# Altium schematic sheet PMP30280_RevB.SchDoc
size 431 x 279 mm; Date: Not shown in title block; ApprovedBy: Not shown in title block; CheckedBy: Not shown in title block; Author: Not shown in title block; CompanyName: Not shown in title block; Engineer: Not shown in title block; Organization: Not shown in title block; Address1: Not shown in title block; Address2: Not shown in title block; Address3: Not shown in title block; Address4: Not shown in title block; DocumentNumber: 1; Revision: Use project parameter SCH_Rev; SheetNumber: 2; SheetTotal: 3; PageSetup: Record=PageOptions¦CenterHorizontal=True¦CenterVertical=True¦PrintScale=1.00¦XCorrection=1.00¦YCorrection=1.00¦PrintKind=0¦BorderSize=5000000¦LeftOffset=0¦BottomOffset=0¦Orientation=2¦PaperLength=1000¦PaperWidth=1000¦Scale=100¦PaperSource=15¦PrintQuality=600¦MediaType=1¦DitherType=10¦PaperKind=Letter¦PrintScaleMode=1
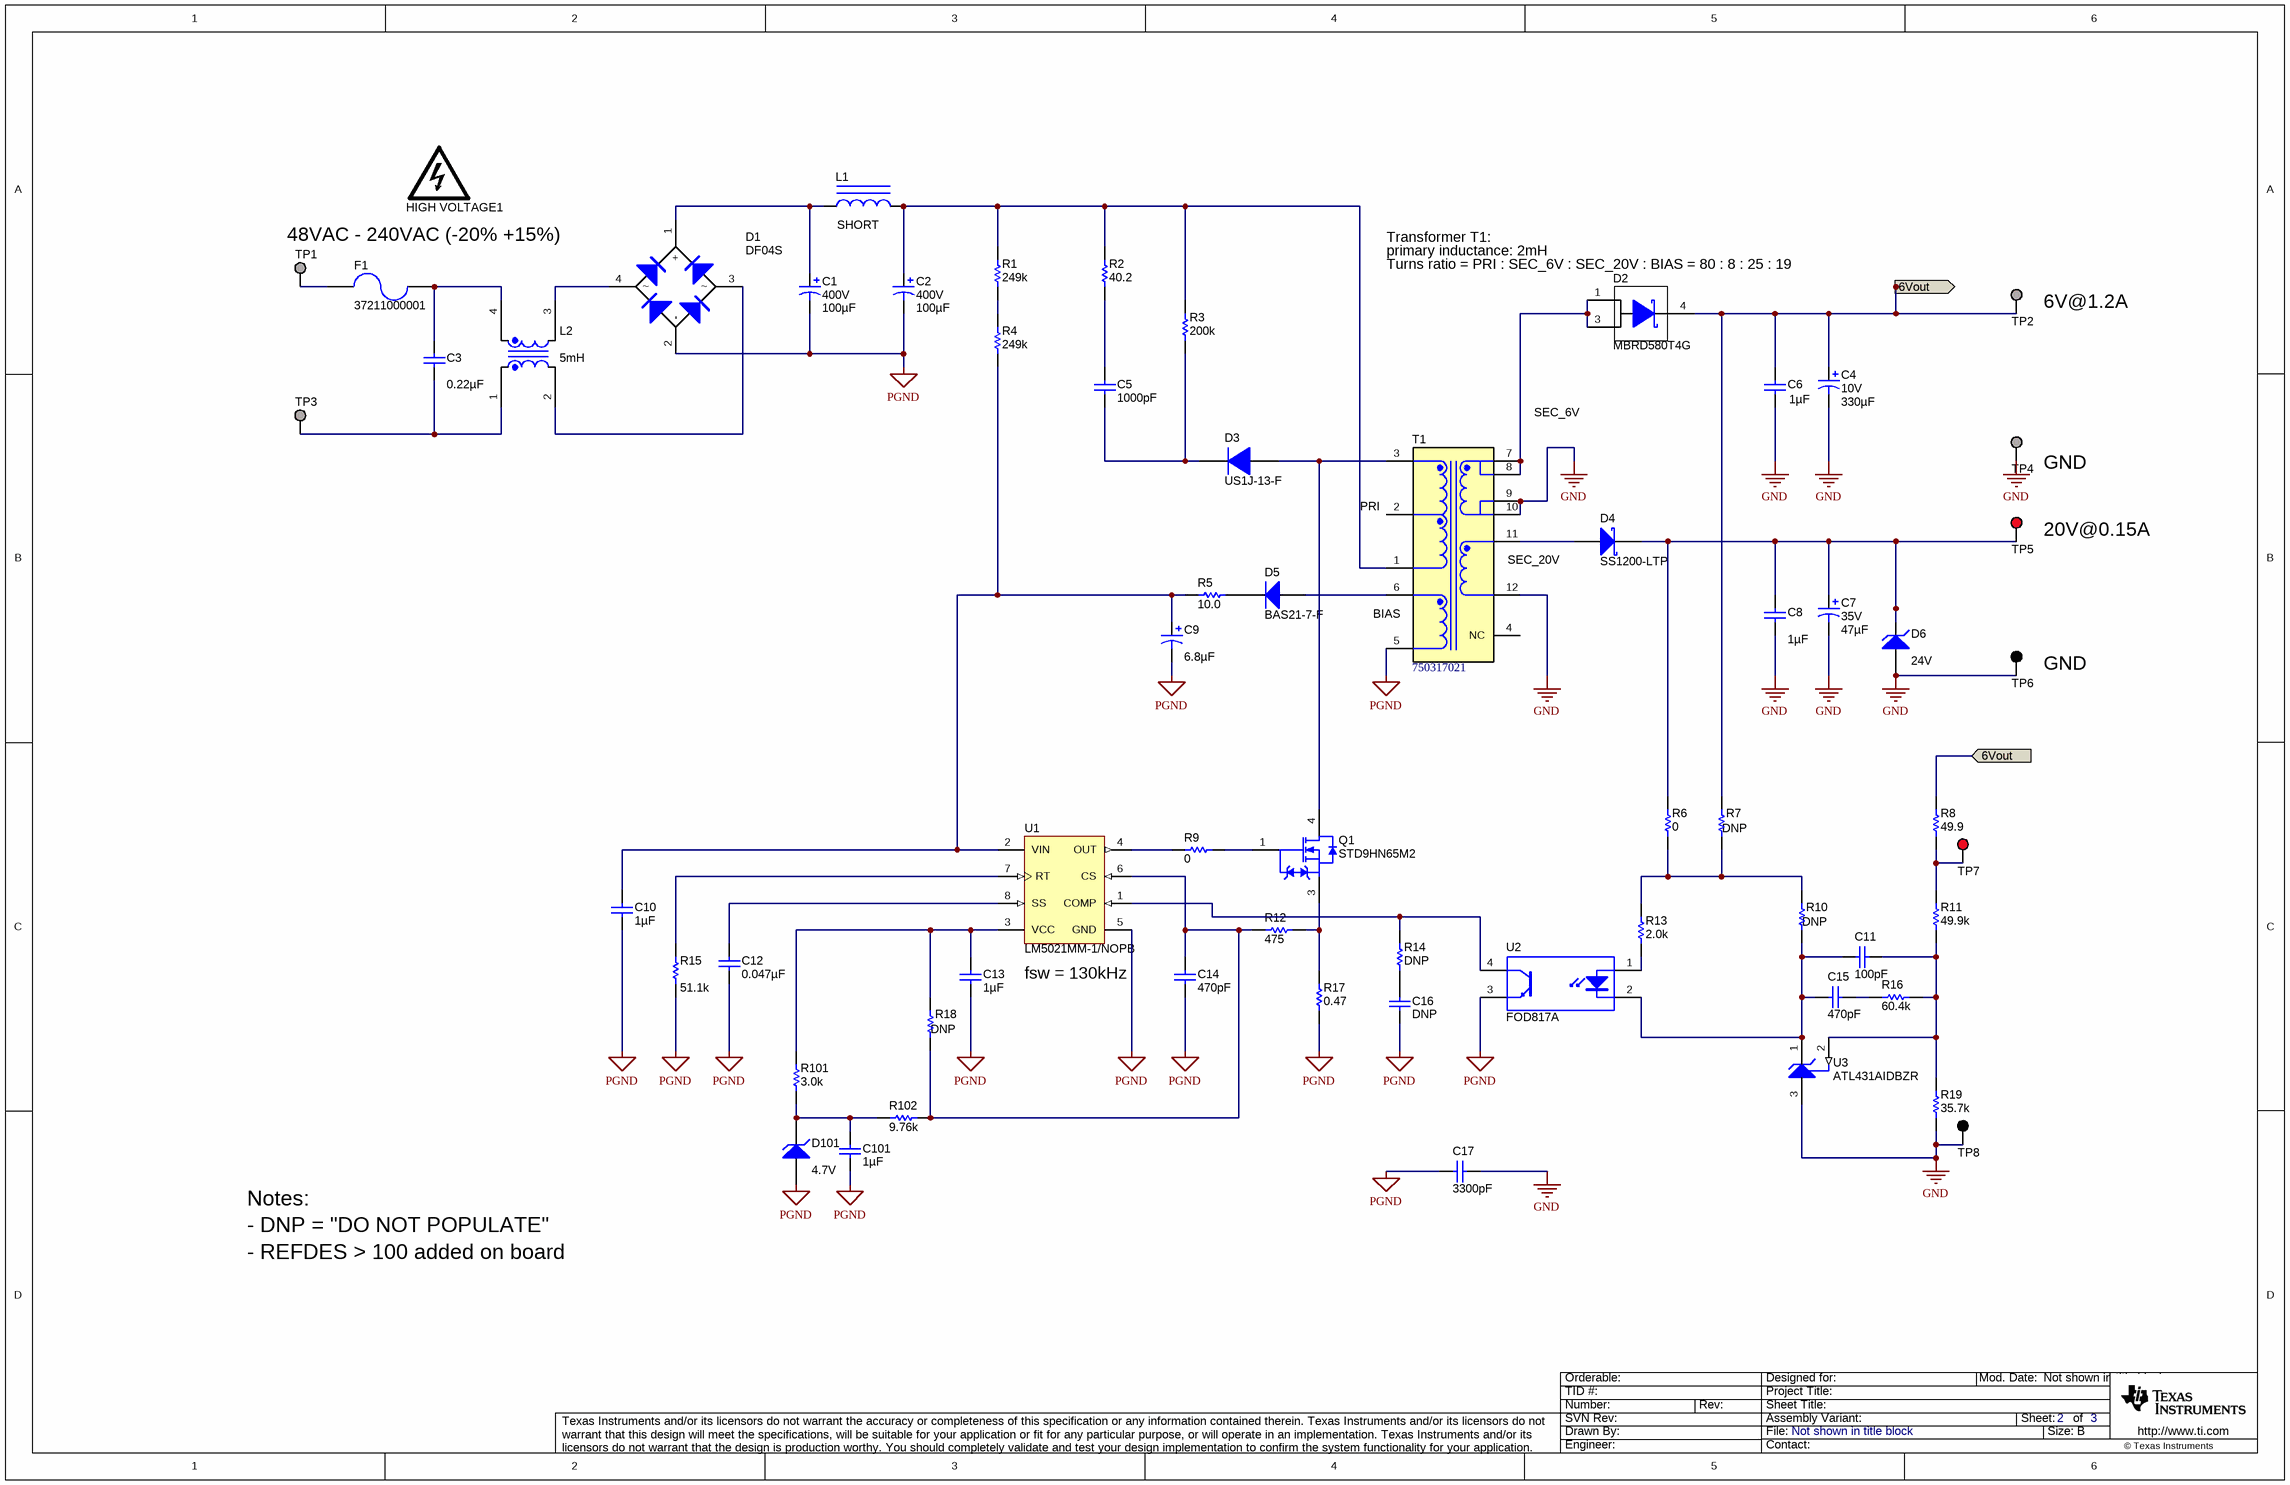
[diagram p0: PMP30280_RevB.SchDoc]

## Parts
C1  VDC_V: 400V  ValueDisplayed: 100µF  [Chemi-Con_1800x3150]  (hidden comment: EKXG401ELL101MMN3S)
C2  VDC_V: 400V  ValueDisplayed: 100µF  [Chemi-Con_1800x3150]  (hidden comment: EKXG401ELL101MMN3S)
C3  ValueDisplayed: 0.22µF  [B32922_12.5mm]  (hidden comment: B32922C3224K)
C4  VDC_V: 10V  ValueDisplayed: 330µF  [WCAP-PSHP_800x770]  (hidden comment: 875115250001)
C5  ValueDisplayed: 1000pF  [0805_HV]  (hidden comment: C0805C102JBRACTU)
C6  ValueDisplayed: 1µF  [0805_HV]  (hidden comment: 0805ZC105KAT2A)
C7  VDC_V: 35V  ValueDisplayed: 47µF  [Chemi-Con_500x1100]  (hidden comment: EKZN350ELL470ME11D)
C8  ValueDisplayed: 1µF  [0805_HV]  (hidden comment: GRM21BR71H105KA12L)
C9  ValueDisplayed: 6.8µF  [SM_RADIAL_C]  (hidden comment: EEE-FC1V6R8R)
C10  ValueDisplayed: 1µF  [0805_HV]  (hidden comment: 08055C105KAT2A)
C11  ValueDisplayed: 100pF  [0603]  (hidden comment: 06035A101FAT2A)
C12  ValueDisplayed: 0.047µF  [0603]  (hidden comment: C1608X7R1H473K080AA)
C13  ValueDisplayed: 1µF  [0805_HV]  (hidden comment: 08055C105KAT2A)
C14  ValueDisplayed: 470pF  [0603]  (hidden comment: 06035A471JAT2A)
C15  ValueDisplayed: 470pF  [0805_HV]  (hidden comment: 08055C471KAT2A)
C16  value DNP  [0603_HV]  (hidden comment: Used in BOM report)
C17  ValueDisplayed: 3300pF  [KX_1000x700]  (hidden comment: DE1E3KX332MN4AP01F)
C101  ValueDisplayed: 1µF  [0805_HV]  (hidden comment: 0805ZC105KAT2A)
D1  DF04S  [DF-S]
D2  MBRD580T4G  [DPAK]
D3  US1J-13-F  [SMA]
D4  SS1200-LTP  [SMA]
D5  BAS21-7-F  [SOT-23]
D6  value 24V  [SOD-123]  (hidden comment: MMSZ5252B-7-F)
D101  value 4.7V  [SOD-123]  (hidden comment: BZT52C4V7-13-F)
F1  37211000001  [FUSE_372]
HIGH_VOLTAGE1  DANGER HIGH VOLTAGE  [IEC_HighVoltage_Small]  (value not drawn)  (no BOM)
L1  value SHORT  [WE-TI_8075_STU]  (hidden comment: DNP)
L2  ValueDisplayed: 5mH  [WE-CMB_Type_S]  (hidden comment: 744821150)
Q1  STD9HN65M2  [DPAK]
R1  ValueDisplayed: 249k  [1206]  (hidden comment: CRCW1206249KFKEA)
R2  ValueDisplayed: 40.2  [1206]  (hidden comment: CRCW120640R2FKEA)
R3  ValueDisplayed: 200k  [1206]  (hidden comment: CRCW1206200KJNEA)
R4  ValueDisplayed: 249k  [1206]  (hidden comment: CRCW1206249KFKEA)
R5  ValueDisplayed: 10.0  [0805_HV]  (hidden comment: CRCW080510R0FKEA)
R6  ValueDisplayed: 0  [0603]  (hidden comment: CRCW06030000Z0EA)
R7  value DNP  [0603]  (hidden comment: Used in BOM report)
R8  ValueDisplayed: 49.9  [0603]  (hidden comment: CRCW060349R9FKEA)
R9  ValueDisplayed: 0  [0805_HV]  (hidden comment: CRCW08050000Z0EA)
R10  value DNP  [0603]  (hidden comment: Used in BOM report)
R11  ValueDisplayed: 49.9k  [0603]  (hidden comment: CRCW060349K9FKEA)
R12  ValueDisplayed: 475  [0603]  (hidden comment: CRCW0603475RFKEA)
R13  ValueDisplayed: 2.0k  [0603]  (hidden comment: CRCW06032K00JNEA)
R14  value DNP  [0603_HV]  (hidden comment: Used in BOM report)
R15  ValueDisplayed: 51.1k  [0603]  (hidden comment: CRCW060351K1FKEA)
R16  ValueDisplayed: 60.4k  [0603]  (hidden comment: CRCW060360K4FKEA)
R17  ValueDisplayed: 0.47  [1206]  (hidden comment: ERJ-8RQFR47V)
R18  value DNP  [0603_HV]  (hidden comment: Used in BOM report)
R19  ValueDisplayed: 35.7k  [0603]  (hidden comment: CRCW060335K7FKEA)
R101  ValueDisplayed: 3.0k  [0805_HV]  (hidden comment: CRCW08053K00JNEA)
R102  ValueDisplayed: 9.76k  [0603]  (hidden comment: CRCW06039K76FKEA)
T1  750317021  [Wurth_EFD25_6008]
TP1  Suggest using a net name here  [Keystone1503-2]  (value not drawn)
TP2  Suggest using a net name here  [Keystone1503-2]  (value not drawn)
TP3  Suggest using a net name here  [Keystone1503-2]  (value not drawn)
TP4  Suggest using a net name here  [Keystone1503-2]  (value not drawn)
TP5  5000  [Keystone5000]  (value not drawn)
TP6  5001  [Keystone5001]  (value not drawn)
TP7  5000  [Keystone5000]  (value not drawn)
TP8  5001  [Keystone5001]  (value not drawn)
U1  LM5021MM-1/NOPB  [MUA08A_N]
U2  FOD817A  [DIP-4]
U3  ATL431AIDBZR  [DBZ0003A_N]

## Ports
6Vout (in), 6Vout (out)

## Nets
GND: C4.2(-) C6.2 C7.2(-) C8.2 C17.1 D6.2(A) R19.1 T1.9 T1.10 T1.12 TP4.1 TP6.1 TP8.1 U3.3(ANODE)
PGND: C1.2(-) C2.2(-) C9.2(-) C10.2 C12.2 C13.2 C14.2 C16.2 C17.2 C101.2 D1.2(-) D101.2(A) R15.1 R17.1 T1.5 U1.5(GND) U2.3(E)
6Vout: C4.1(+) C6.1 D2.4(K) R7.2 R8.2 TP2.1 ; port 6Vout
NetC1_1: C1.1(+) D1.1(+) L1.1
NetC2_1: C2.1(+) L1.2 R1.2 R2.2 R3.2 T1.1
NetC3_1: C3.1 F1.1 L2.4
NetC3_2: C3.2 L2.1 TP3.1
NetC5_1: C5.1 R2.1
NetC5_2: C5.2 D3.1(K) R3.1
NetC7_1: C7.1(+) C8.1 D4.1(K) D6.1(K) R6.2 TP5.1
NetC9_1: C9.1(+) C10.1 R4.1 R5.1 U1.2(VIN)
NetC11_1: C11.1 R11.1 R16.2 R19.2 U3.2(REF)
NetC11_2: C11.2 C15.2 R10.1 U2.2(K) U3.1(CATHODE)
NetC12_1: C12.1 U1.8(SS)
NetC13_1: C13.1 R18.2 R101.2 U1.3(VCC)
NetC14_1: C14.1 R12.1 R18.1 R102.1 U1.6(CS)
NetC15_1: C15.1 R16.1
NetC16_1: C16.1 R14.1
NetC101_1: C101.1 D101.1(K) R101.1 R102.2
NetD1_3: D1.3 L2.2
NetD1_4: D1.4 L2.3
NetD2_1: D2.1(A) D2.3(A) T1.7 T1.8
NetD3_2: D3.2(A) Q1.4(D) T1.3
NetD4_2: D4.2(A) T1.11
NetD5_1: D5.1(A) T1.6
NetD5_3: D5.3(K) R5.2
NetF1_2: F1.2 TP1.1
NetQ1_1: Q1.1(G) R9.2
NetQ1_3: Q1.3(S) R12.2 R17.2
NetR1_1: R1.1 R4.2
NetR6_1: R6.1 R7.1 R10.2 R13.2
NetR8_1: R8.1 R11.2 TP7.1
NetR9_1: R9.1 U1.4(OUT)
NetR13_1: R13.1 U2.1(A)
NetR14_2: R14.2 U1.1(COMP) U2.4(C)
NetR15_2: R15.2 U1.7(RT)

Not connected (* = marked no-connect by the designer): T1 2 4(NC)

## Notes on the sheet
- 48VAC - 240VAC (-20% +15%)
- primary inductance: 2mH
- (near D2) Turns ratio = PRI : SEC_6V : SEC_20V : BIAS = 80 : 8 : 25 : 19
- Transformer T1:
- (near TP2) 6V@1.2A
- SEC_6V
- (near TP4) GND
- (near T1) PRI
- (near T1) SEC_20V
- (near TP5) 20V@0.15A
- (near T1) BIAS
- (near TP6) GND
- fsw = 130kHz
- Notes:
- - DNP = "DO NOT POPULATE"
- - REFDES > 100 added on board

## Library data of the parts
C1 C2 = CMP-0074694-1: CAP, AL, 100 µF, 400 V, +/- 20%, TH; Manufacturer: Chemi-Con; TaMin_C: -40°C; Polarized: Y; SizeAreaWB_mm2: 400.0; U/M: EA; Value: 100uF; TaMax_C: 105°C; SizeZ_mm: 33.0; SizeX_mm: 18.0; Cap_Case: 18x31.5; SizeArea_mm2: 324.0; CompType: Capacitor; AEC Qualified: N; IRMS_A: 1.72A; AEC Category: Q200
C3 = B32922C3224K: CAP, Film, 0.22 µF, 630 V,+/- 10%, TH; Manufacturer: TDK; Polarized: N; CompType: Capacitor; Value: 0.22uF; U/M: EA; Cap_F: 0.00000022; Tolerance_%: 10; VDC_V: 630; Value2: 630V; TaMax_C: 110; SizeAreaWB_mm2: 180; SizeArea_mm2: 126; SizeX_mm: 18; SizeY_mm: 7; SizeZ_mm: 12.5; AEC Category: Q200
C4 = CMP-0001609-3: CAP, Aluminum Polymer, 330 µF, 10 V,+/- 20%, 0.02 ohm, D8xL7.7mm SMD; Manufacturer: Wurth Elektronik; TaMax_C: 105°C; SizeX_mm: 9.0; SizeY_mm: 8.3; TaMin_C: -55°C; CompType: Capacitor; SizeZ_mm: 7.7; AEC Qualified: N; Value: 330uF; SizeArea_mm2: 74.7; AEC Category: Q200; SizeAreaWB_mm2: 113.3; U/M: EA; Polarized: Y; Cap_Case: 8X7.7mm; ESR_ohm: 0.02
C5 = C0805C102JBRACTU: CAP, CERM, 1000 pF, 630 V,+/- 5%, X7R, 0805; Manufacturer: Kemet; Polarized: N; CompType: Capacitor; Value: 1000pF; U/M: EA; Cap_F: 0.000000001; Tolerance_%: 5; VDC_V: 630; Value2: 630V; TaMin_C: -55; TaMax_C: 125; Cap_Case: 0805; SizeArea_mm2: 2.5; SizeAreaWB_mm2: 6.75; SizeX_mm: 2; SizeY_mm: 1.25; SizeZ_mm: 1.45; AEC Category: Q200
C6 C101 = 0805ZC105KAT2A: CAP, CERM, 1 µF, 10 V,+/- 10%, X7R, 0805; Manufacturer: AVX; Polarized: N; CompType: Capacitor; Value: 1uF; U/M: EA; Cap_F: 0.000001; Tolerance_%: 10; ESR_ohm: 0.008; Value1: 0.008 ohm; Value2: 10V; TaMin_C: -55; TaMax_C: 125; Cap_Case: 0805; SizeArea_mm2: 2.5; SizeAreaWB_mm2: 6.75; SizeX_mm: 2; SizeY_mm: 1.25; SizeZ_mm: 1.45; AEC Category: Q200; Green_Lifecycle: Not Set; Green_REACh: Incomplete
C7 = CMP-0074695-1: CAP, AL, 47 µF, 35 V, +/- 20%, 0.38 ohm, TH; Manufacturer: Chemi-Con; TaMin_C: -40°C; ESR_ohm: 3.8d; Polarized: Y; SizeAreaWB_mm2: 49.0; U/M: EA; Value: 47uF; TaMax_C: 105°C; SizeZ_mm: 12.5; SizeX_mm: 5.0; Cap_Case: 5x11; SizeArea_mm2: 25.0; CompType: Capacitor; AEC Qualified: N; IRMS_A: 4.5dA; AEC Category: Q200
C8 = GRM21BR71H105KA12L: CAP, CERM, 1 µF, 50 V,+/- 10%, X7R, 0805; Manufacturer: MuRata; Polarized: N; CompType: Capacitor; Value: 1uF; U/M: EA; Cap_F: 0.000001; Tolerance_%: 10; Value1: Unknown; VDC_V: 50; Value2: 50V; TaMin_C: -55; TaMax_C: 125; Cap_Case: 0805; SizeArea_mm2: 2.5; SizeAreaWB_mm2: 6.75; SizeX_mm: 2; SizeY_mm: 1.25; SizeZ_mm: 1.45; AEC Category: Q200; Green_Lifecycle: Active; Green_REACh: Passed
C9 = EEE-FC1V6R8R: CAP, AL, 6.8 µF, 35 V, +/- 20%, 1.8 ohm, SMD; Manufacturer: Panasonic; Polarized: Y; CompType: Capacitor; Value: 6.8uF; U/M: EA; Cap_F: 0.0000068; Tolerance_%: 20; Value1: 1.8 ohm; VDC_V: 35; Value2: 35V; ESR_ohm: 1.8; IRMS_A: 0.08; TaMin_C: -40; TaMax_C: 105; Cap_Case: C; SizeAreaWB_mm2: 62.05; SizeArea_mm2: 34.45; SizeX_mm: 6.5; SizeY_mm: 5.3; SizeZ_mm: 5.4; AEC Category: Q200
C10 = 08055C105KAT2A: CAP, CERM, 1 µF, 50 V,+/- 10%, X7R, 0805; Manufacturer: AVX; Polarized: N; CompType: Capacitor; Value: 1uF; U/M: EA; Cap_F: 0.000001; Tolerance_%: 10; VDC_V: 50; Value2: 50V; TaMin_C: -55; TaMax_C: 125; Cap_Case: 0805; SizeArea_mm2: 2.5; SizeAreaWB_mm2: 6.75; SizeX_mm: 2; SizeY_mm: 1.25; SizeZ_mm: 1.45; AEC Category: Q200; Green_Lifecycle: Active; Green_REACh: Passed
C11 = 06035A101FAT2A: CAP, CERM, 100 pF, 50 V,+/- 1%, C0G/NP0, 0603; Manufacturer: AVX; Polarized: N; CompType: Capacitor; Value: 100pF; U/M: EA; Cap_F: 0.0000000001; Tolerance_%: 1; VDC_V: 50; Value2: 50V; TaMin_C: -55; TaMax_C: 125; AEC Category: Q200; SizeArea_mm2: 1.28; SizeAreaWB_mm2: 4.68; SizeX_mm: 1.6; SizeY_mm: 0.8; Green_Lifecycle: Active; Green_REACh: Passed
C12 = C1608X7R1H473K080AA: CAP, CERM, 0.047 µF, 50 V,+/- 10%, X7R, 0603; Manufacturer: TDK; Polarized: N; CompType: Capacitor; Value: 0.047uF; U/M: EA; Cap_F: 0.000000047; Tolerance_%: 10; ESR_ohm: 0.049007; Value1: 0.049007 ohm; VDC_V: 50; Value2: 50V; IRMS_A: 0.767528; TaMin_C: -55; TaMax_C: 125; SizeArea_mm2: 1.28; SizeAreaWB_mm2: 4.68; SizeX_mm: 1.6; SizeY_mm: 0.8; SizeZ_mm: 1; AEC Category: Q200; Green_Lifecycle: NRND; Green_REACh: Passed
C13 = 08055C105KAT2A: CAP, CERM, 1 µF, 50 V, +/- 10%, X7R, 0805; Manufacturer: AVX; Polarized: N; CompType: Capacitor; Value: 1uF; U/M: EA; Cap_F: 0.000001; Tolerance_%: 10; Value1: Unknown; VDC_V: 50; Value2: 50V; TaMin_C: -55; TaMax_C: 125; Cap_Case: 0805
C14 = 06035A471JAT2A: CAP, CERM, 470 pF, 50 V,+/- 5%, C0G/NP0, 0603; Manufacturer: AVX; Polarized: N; CompType: Capacitor; Value: 470pF; U/M: EA; Cap_F: 0.00000000047; Tolerance_%: 5; ESR_ohm: 0.063; Value1: 0.063 ohm; VDC_V: 50; Value2: 50V; TaMin_C: -55; TaMax_C: 125; SizeArea_mm2: 1.28; SizeAreaWB_mm2: 4.68; SizeX_mm: 1.6; SizeY_mm: 0.8; SizeZ_mm: 1; AEC Category: Q200; Green_Lifecycle: Active; Green_REACh: Passed
C15 = 08055C471KAT2A: CAP, CERM, 470 pF, 50 V,+/- 10%, X7R, 0805; Manufacturer: AVX; Polarized: N; CompType: Capacitor; Value: 470pF; U/M: EA; Cap_F: 0.00000000047; Tolerance_%: 10; ESR_ohm: 0.454; Value1: 0.454 ohm; VDC_V: 50; Value2: 50V; TaMin_C: -55; TaMax_C: 125; Cap_Case: 0805; SizeArea_mm2: 2.5; SizeAreaWB_mm2: 6.75; SizeX_mm: 2; SizeY_mm: 1.25; SizeZ_mm: 1.45; AEC Category: Q200; Green_Lifecycle: Not Set; Green_REACh: Incomplete
C16 = Capacitor: CAP, CERM, xxxF, xxV, [TempCo], xx%, [PackageReference]; Polarized: N; U/M: EA
C17 = DE1E3KX332MN4AP01F: CAP, CERM, 3300 pF, X1 250 VAC/Y1 300 VAC, +/- 20%, E, D10xT7mm; Manufacturer: MuRata; Polarized: N; CompType: Capacitor; Value: 3300pF; U/M: EA; Cap_F: 0.0000000033; Tolerance_%: 20; TaMin_C: -40; TaMax_C: 125; Cap_Case: 10x7mm; SizeArea_mm2: 70; SizeAreaWB_mm2: 108; SizeX_mm: 10; SizeY_mm: 7; SizeZ_mm: 13; AEC Category: Q200; AC_Safety: X1Y1; VAC_X: 250; VAC_Y: 300
D1 = DF06S-E3: Diode, Switching-Bridge, 400 V, 1.5A,; Manufacturer: Vishay-Semiconductor; U/M: EA; Vf_V: 1.1; Value: 600V; Value1: 1A; Value2: 1.1V; Io_A: 1; Vr_V: 400; TJmax_C: 150; RJC_CperW: 15; SizeAreaWB_mm2: 98.794; SizeArea_mm2: 62.974; SizeX_mm: 7.4; SizeY_mm: 8.51; SizeZ_mm: 3.4; AEC Category: Q101; Green_Lifecycle: Not Set; Green_REACh: Incomplete; Voltage - Peak Reverse (Max): 400V; Current - Reverse Leakage @ Vr: 5µA @ 400V
D2 = MBRD360T4G: Diode, Schottky, 80 V, DPAK; Manufacturer: SMC Diode Solutions; U/M: EA; Vf_V: 0.6; Value: 60V; Value1: 3A; Value2: 0.6V; Io_A: 3; Vr_V: 60; TJmax_C: 150; RJC_CperW: 6; SizeAreaWB_mm2: 101.7114; SizeArea_mm2: 64.8114; SizeX_mm: 9.91; SizeY_mm: 6.54; SizeZ_mm: 2.29; AEC Category: Q101; Green_Lifecycle: Not Set; Green_REACh: Incomplete; Speed: Fast Recovery =< 500ns, > 200mA (Io); Current - Reverse Leakage @ Vr: 1mA @ 80V; Capacitance @ Vr, F: 300pF @ 5V, 1MHz
D3 = US1J-13-F: Diode, Ultrafast, 600 V, 1 A, SMA; Manufacturer: Diodes Inc.; U/M: EA; Vf_V: 1.7; Value: 600V; Value1: 1A; Value2: 1.7V; Io_A: 1; Vr_V: 600; TJmax_C: 150; SizeAreaWB_mm2: 37.3428; SizeArea_mm2: 16.3228; SizeX_mm: 5.59; SizeY_mm: 2.92; SizeZ_mm: 2.87; AEC Category: Q101; Green_Lifecycle: Active; Green_REACh: Passed
D4 = SS1200-LTP: Diode, Schottky, 200 V, 1 A, SMA; Manufacturer: Micro Commercial Components; U/M: EA; Vf_V: 0.92; Value: 200V; Value1: 1A; Value2: 0.92V; Io_A: 1; Vr_V: 200; TJmax_C: 150; SizeAreaWB_mm2: 37.3428; SizeArea_mm2: 16.3228; SizeX_mm: 5.59; SizeY_mm: 2.92; SizeZ_mm: 2.87; AEC Category: Q101; AEC Qualified: N
D5 = BAS21-7-F: Diode, Switching, 200 V, 0.2 A, SOT-23; Manufacturer: Diodes Inc.; U/M: EA; Vf_V: 1.25; Value: 200V; Value1: 0.2A; Value2: 1.25V; Io_A: 0.2; Vr_V: 200; TJmax_C: 150; RJC_CperW: 500
D6 = MMSZ5252B-7-F: Diode, Zener, 24 V, 500 mW, SOD-123; Manufacturer: Diodes Inc.; SymbolCreator: a0412235; U/M: EA; Power_W: 0.5; Vz_V: 24; Value1: 0.5W; RJA_CperW: 350; SizeAreaWB_mm2: 13.095; SizeArea_mm2: 6.545; SizeX_mm: 3.85; SizeY_mm: 1.7; SizeZ_mm: 1.35; AEC Category: Q101
D101 = BZT52C4V7-13-F: Diode, Zener, 4.7 V, 500 mW, SOD-123; Manufacturer: Diodes Inc.; SymbolCreator: a0412235; U/M: EA; Power_W: 0.5; Vz_V: 4.7; Value1: 0.5W; RJA_CperW: 338; SizeAreaWB_mm2: 13.095; SizeArea_mm2: 6.545; SizeX_mm: 3.85; SizeY_mm: 1.7; SizeZ_mm: 1.35; AEC Category: Q101; Green_Lifecycle: Active; Green_REACh: Passed
F1 = 37211000001: Fuse, 1 A, 250VAC/VDC, TH; Manufacturer: Littelfuse; VDC_V: 250; Irating_A: 1
HIGH_VOLTAGE1 = IEC_HighVoltage: IEC 61010-1 High Voltage Warning; SymbolCreator: a0412235
L1 = 744732681: Inductor, Unshielded Drum Core, Metal Composite, 680 µH, 0.42 A, 2.2 ohm, TH; Manufacturer: Wurth Elektronik; Ind_H: 680.0E-6; Imax_A: 0.42; Irms: 0.42A @ 40C rise; Isat: 0.75A @ 10% inductance drop; DCR_ohm: 2.2; Value1: 2.2 ohm; Value2: 0.42A; SizeAreaWB_mm2: 132.25; SizeArea_mm2: 90.25; SizeX_mm: 9.5; SizeZ_mm: 8; AEC Category: Q200; AEC Qualified: N
L2 = 744822110: Coupled inductor, 5mH; Manufacturer: Wurth Elektronik; SymbolCreator: a0412235; Ind_H: 10.0E-3; DCR_ohm: 0.36
Q1 = CMP-0001614-1: MOSFET, N-CH, 650 V, 5.5 A, DPAK; Alternate Manufacturer: None; Manufacturer: STMicroelectronics; QgTyp_nC: 11.5; SizeAreaWB_mm2: 101.7114; Vgs_V: 25V; Value1: ? ohm; VdsMax_V: 650V; U/M: EA; Value: 650V; IdsMax_A: 5.5A; SizeZ_mm: 2.29; SizeX_mm: 9.91; SizeY_mm: 6.54; Value2: 11.5 nC; SizeArea_mm2: 64.8114; ChType: N; AEC Category: Q101
R1 R4 = CRCW1206249KFKEA: RES, 249 k, 1%, 0.25 W, 1206; Manufacturer: Vishay-Dale; CompType: Resistor; Value: 249k; Res_ohm: 249000; Tolerance_%: 1; Power_W: 0.25; Value2: 0.25W; VDC_V: 200; TempCo: 100 ppm/C; EIA_Code: E96; U/M: EA; SizeArea_mm2: 5.12; SizeX_mm: 3.2; SizeY_mm: 1.6; SizeZ_mm: 1.35; AEC Category: Q200
R2 = CRCW120640R2FKEA: RES, 40.2, 1%, 0.25 W, 1206; Manufacturer: Vishay-Dale; CompType: Resistor; Value: 40.2; Value_Code: 40R2; Tolerance_%: 1; Power_W: 0.25; Value2: 0.25W; VDC_V: 200; TempCo: 100 ppm/C; SizeArea_mm2: 5.12; SizeX_mm: 3.2; SizeY_mm: 1.6; SizeZ_mm: 1.35; EIA_Code: E96; U/M: EA; AEC Category: Q200; Green_Lifecycle: Active; Green_REACh: Passed
R3 = CRCW1206200KJNEA: RES, 200 k, 5%, 0.25 W, 1206; Manufacturer: Vishay-Dale; CompType: Resistor; Value: 200k; Res_ohm: 200000; Tolerance_%: 5; Power_W: 0.25; Value2: 0.25W; VDC_V: 200; TempCo: 200 ppm/C; SizeArea_mm2: 5.12; SizeX_mm: 3.2; SizeY_mm: 1.6; SizeZ_mm: 1.35; EIA_Code: E24; U/M: EA; AEC Category: Q200
R5 = CRCW080510R0FKEA: RES, 10.0, 1%, 0.125 W, 0805; Manufacturer: Vishay-Dale; CompType: Resistor; Value: 10.0; Res_ohm: 10; Value_Code: 10R0; Tolerance_%: 1; Power_W: 0.125; Value2: 0.125W; VDC_V: 150; TempCo: 100 ppm/C; EIA_Code: E96; U/M: EA
R6 = CRCW06030000Z0EA: RES, 0, 5%, 0.1 W, 0603; Manufacturer: Vishay-Dale; CompType: Resistor; Value: 0; Value_Code: 0000; Tolerance_%: 5; Power_W: 0.1; Value2: 0.1W; VDC_V: 75; TempCo: 200 ppm/C; EIA_Code: E24; U/M: EA
R7 R10 R14 R18 = Resistor: RES, xxx ohm, x%, xW, [PackageReference]; U/M: EA
R8 = CRCW060349R9FKEA: RES, 49.9, 1%, 0.1 W, 0603; Manufacturer: Vishay-Dale; CompType: Resistor; Value: 49.9; Value_Code: 49R9; Tolerance_%: 1; Power_W: 0.1; Value2: 0.1W; VDC_V: 75; TempCo: 100 ppm/C; EIA_Code: E96; U/M: EA
R9 = CRCW08050000Z0EA: RES, 0, 5%, 0.125 W, 0805; Manufacturer: Vishay-Dale; CompType: Resistor; Value: 0; Value_Code: 0000; Tolerance_%: 5; Power_W: 0.125; Value2: 0.125W; VDC_V: 150; TempCo: 200 ppm/C; EIA_Code: E24; U/M: EA
R11 = CRCW060349K9FKEA: RES, 49.9 k, 1%, 0.1 W, 0603; Manufacturer: Vishay-Dale; CompType: Resistor; Value: 49.9k; Res_ohm: 49900; Value_Code: 49k9; Tolerance_%: 1; Power_W: 0.1; Value2: 0.1W; VDC_V: 75; TempCo: 100 ppm/C; EIA_Code: E96; U/M: EA; SizeArea_mm2: 1.28; SizeX_mm: 1.6; SizeY_mm: 0.8; AEC Category: Q200; Green_Lifecycle: Active; Green_REACh: Passed
R12 = CRCW0603475RFKEA: RES, 475, 1%, 0.1 W, 0603; Manufacturer: Vishay-Dale; CompType: Resistor; Value: 475; Value_Code: 475R; Tolerance_%: 1; Power_W: 0.1; Value2: 0.1W; VDC_V: 75; TempCo: 100 ppm/C; SizeArea_mm2: 1.28; SizeX_mm: 1.6; SizeY_mm: 0.8; EIA_Code: E96; U/M: EA; AEC Category: Q200; Green_Lifecycle: Active; Green_REACh: Passed
R13 = CRCW06032K00JNEA: RES, 2.0 k, 5%, 0.1 W, 0603; Manufacturer: Vishay-Dale; CompType: Resistor; Value: 2.0k; Res_ohm: 2000; Value_Code: 2k00; Tolerance_%: 5; Power_W: 0.1; Value2: 0.1W; VDC_V: 75; TempCo: 200 ppm/C; EIA_Code: E24; U/M: EA
R15 = CRCW060351K1FKEA: RES, 51.1 k, 1%, 0.1 W, 0603; Manufacturer: Vishay-Dale; CompType: Resistor; Value: 51.1k; Res_ohm: 51100; Value_Code: 51k1; Tolerance_%: 1; Power_W: 0.1; Value2: 0.1W; VDC_V: 75; TempCo: 100 ppm/C; SizeArea_mm2: 1.28; SizeX_mm: 1.6; SizeY_mm: 0.8; EIA_Code: E96; U/M: EA; AEC Category: Q200; Green_Lifecycle: Active; Green_REACh: Passed
R16 = CRCW060360K4FKEA: RES, 60.4 k, 1%, 0.1 W, 0603; Manufacturer: Vishay-Dale; CompType: Resistor; Value: 60.4k; Res_ohm: 60400; Value_Code: 60k4; Tolerance_%: 1; Power_W: 0.1; Value2: 0.1W; VDC_V: 75; TempCo: 100 ppm/C; SizeArea_mm2: 1.28; SizeX_mm: 1.6; SizeY_mm: 0.8; EIA_Code: E96; U/M: EA; AEC Category: Q200; Green_Lifecycle: Active; Green_REACh: Passed
R17 = ERJ-8RQFR47V: RES, 0.47, 1%, 0.25 W, 1206; Manufacturer: Panasonic; CompType: Resistor; Value: 0.47; Value_Code: R470; Tolerance_%: 1; Power_W: 0.25; Value2: 0.25W; TempCo: 250 ppm/C; SizeArea_mm2: 5.12; SizeX_mm: 3.2; SizeY_mm: 1.6; SizeZ_mm: 1.35; EIA_Code: E96; U/M: EA; AEC Category: Q200
R19 = CRCW060335K7FKEA: RES, 35.7 k, 1%, 0.1 W, 0603; Manufacturer: Vishay-Dale; CompType: Resistor; Value: 35.7k; Res_ohm: 35700; Value_Code: 35k7; Tolerance_%: 1; Power_W: 0.1; Value2: 0.1W; VDC_V: 75; TempCo: 100 ppm/C; EIA_Code: E96; U/M: EA; SizeArea_mm2: 1.28; SizeX_mm: 1.6; SizeY_mm: 0.8; AEC Category: Q200; Green_Lifecycle: Active; Green_REACh: Passed
R101 = CRCW08053K00JNEA: RES, 3.0 k, 5%, 0.125 W, 0805; Manufacturer: Vishay-Dale; CompType: Resistor; Value: 3.0k; Res_ohm: 3000; Value_Code: 3k00; Tolerance_%: 5; Power_W: 0.125; Value2: 0.125W; VDC_V: 150; TempCo: 200 ppm/C; SizeArea_mm2: 2.5; SizeX_mm: 2; SizeY_mm: 1.25; SizeZ_mm: 1.45; EIA_Code: E24; U/M: EA; AEC Category: Q200; Green_Lifecycle: Active; Green_REACh: Passed
R102 = CRCW06039K76FKEA: RES, 9.76 k, 1%, 0.1 W, 0603; Manufacturer: Vishay-Dale; CompType: Resistor; Value: 9.76k; Res_ohm: 9760; Value_Code: 9k76; Tolerance_%: 1; Power_W: 0.1; Value2: 0.1W; VDC_V: 75; TempCo: 100 ppm/C; SizeArea_mm2: 1.28; SizeX_mm: 1.6; SizeY_mm: 0.8; EIA_Code: E96; U/M: EA; AEC Category: Q200; Green_Lifecycle: Active; Green_REACh: Passed
T1 = CMP-0077154-2: Transformer, 2000 uH, TH; Manufacturer: Wurth Elektronik; SizeX_mm: 33.0; SizeY_mm: 26.3; SizeZ_mm: 14.0; AEC Qualified: N; Value: 2mH; SizeArea_mm2: 867.9; AEC Category: Q200; SizeAreaWB_mm2: 990.5; DCR_ohm: 9.8d; Lp: 2000.0; Ns1toNp: 0.1; Ns2toNp: 0.3125; LeakageInd_H: 10.8µH; Rsec2_ohm: 2.6d; Rsec1_ohm: 0.02
TP1 TP3 = 1503-2: Terminal, Turret, TH, Double; Manufacturer: Keystone; CompType: Turret Terminal; Green_Lifecycle: Active; Green_REACh: Passed
TP2 TP4 = 1503-2: Terminal, Turret, TH, Double; Manufacturer: Keystone; CompType: Turret Terminal; U/M: EA
TP5 TP7 = 5000: Test Point, Miniature, Red, TH; Manufacturer: Keystone; CompType: Test Point Loop; U/M: EA
TP6 TP8 = 5001: Test Point, Miniature, Black, TH; Manufacturer: Keystone; CompType: Test Point Loop; U/M: EA
U1 = LM5021MM-1/NOPB: AC-DC Current Mode PWM Controller, 8-pin MSOP, Pb-Free; Manufacturer: Texas Instruments; PackageTopMarking: ZXTT*21-1; PowerWise: N; CompType: Switcher
U2 = FOD817A: Optocoupler, 5 kV, 80-160% CTR, TH; Manufacturer: Fairchild Semiconductor; CTR (Min): 80%; CTR (Max): 160%; Voltage_Isolation_Vrms: 5000V; SizeAreaWB_mm2: 71.064; SizeArea_mm2: 40.304; SizeX_mm: 8.8; SizeY_mm: 4.58; SizeZ_mm: 5
U3 = ATL431AIDBZR: 2.5V Low Iq Adjustable Precision Shunt Regulator, DBZ0003A (SOT-23-3); Manufacturer: Texas Instruments; SymbolCreator: a0412235; SizeArea_mm2: 7.5; SizeAreaWB_mm2: 14; SizeX_mm: 2.5; SizeY_mm: 3; SizeZ_mm: 1.12; CompType: IC; U/M: EA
